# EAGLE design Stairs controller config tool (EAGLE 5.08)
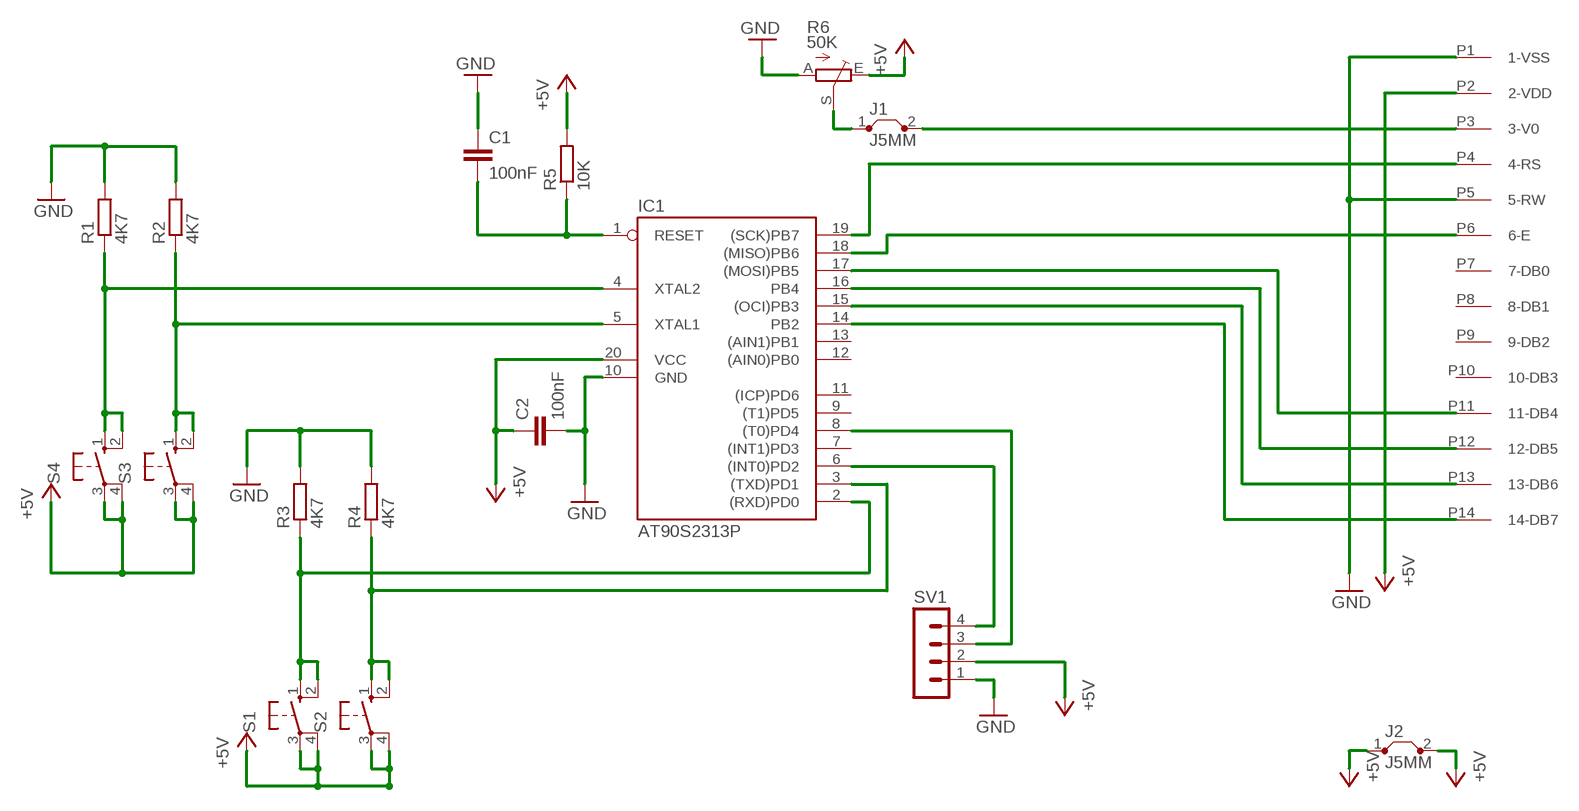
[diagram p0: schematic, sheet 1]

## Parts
C1  100nF  C-EU025-025X050  [C025-025X050]
C2  100nF  C-EU025-025X050  [C025-025X050]
IC1  AT90S2313P  [DIL20]
J1  J5MM  [05]
J2  J5MM  [05]
R1  4K7  R-EU_0207/12  [0207/12]
R2  4K7  R-EU_0207/12  [0207/12]
R3  4K7  R-EU_0207/12  [0207/12]
R4  4K7  R-EU_0207/12  [0207/12]
R5  10K  R-EU_0207/12  [0207/12]
R6  50K  TRIM_EU-B25P  [B25P]
S1  10-XX  [B3F-10XX]
S2  10-XX  [B3F-10XX]
S3  10-XX  [B3F-10XX]
S4  10-XX  [B3F-10XX]
SV1  MA04-1  [MA04-1]
U$1  16X2LCD  [NO_BACKLIGHT]

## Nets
+5V: C2.1 IC1.20(VCC) J2.1 J2.2 R5.2 R6.E S1.3(P) S1.4(P1) S2.3(P) S2.4(P1) S3.3(P) S3.4(P1) S4.3(P) S4.4(P1) SV1.2 U$1.P2(2-VDD)
GND: C1.1 C2.2 IC1.10(GND) R1.2 R2.2 R3.2 R4.2 R6.A SV1.1 U$1.P1(1-VSS) U$1.P5(5-RW)
N$1: IC1.19((SCK)PB7) U$1.P4(4-RS)
N$2: IC1.18((MISO)PB6) U$1.P6(6-E)
N$3: IC1.17((MOSI)PB5) U$1.P11(11-DB4)
N$4: IC1.16(PB4) U$1.P12(12-DB5)
N$5: IC1.15((OCI)PB3) U$1.P13(13-DB6)
N$6: IC1.14(PB2) U$1.P14(14-DB7)
N$7: IC1.4(XTAL2) R1.1 S4.1(S) S4.2(S1)
N$8: IC1.6((INT0)PD2) SV1.4
N$9: IC1.5(XTAL1) R2.1 S3.1(S) S3.2(S1)
N$10: IC1.8((T0)PD4) SV1.3
N$11: IC1.2((RXD)PD0) R3.1 S1.1(S) S1.2(S1)
N$12: IC1.3((TXD)PD1) R4.1 S2.1(S) S2.2(S1)
N$13: C1.2 IC1.1(RESET) R5.1
N$14: J1.1 R6.S
N$15: J1.2 U$1.P3(3-V0)
Unconnected: IC1.7((INT1)PD3) IC1.9((T1)PD5) IC1.11((ICP)PD6) IC1.12((AIN0)PB0) IC1.13((AIN1)PB1) U$1.P7(7-DB0) U$1.P8(8-DB1) U$1.P9(9-DB2) U$1.P10(10-DB3)

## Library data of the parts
C1 C2 = rcl:C-EU: CAPACITOR, European symbol
IC1 = atmel:AT90S2313: MICROCONTROLLER 2 Kbytes FLASH 128 bytes SRAM 128 bytes EEPROM UART
J1 J2 = jumper:J: Bridge
R1-R5 = rcl:R-EU_: RESISTOR, European symbol
R6 = pot:TRIM_EU-: POTENTIOMETER
S1-S4 = switch-omron:10-XX: OMRON SWITCH
SV1 = con-lstb:MA04-1: PIN HEADER
U$1 = lcd_nobacklight:16X2LCD: 16x2 LCD - no backlight

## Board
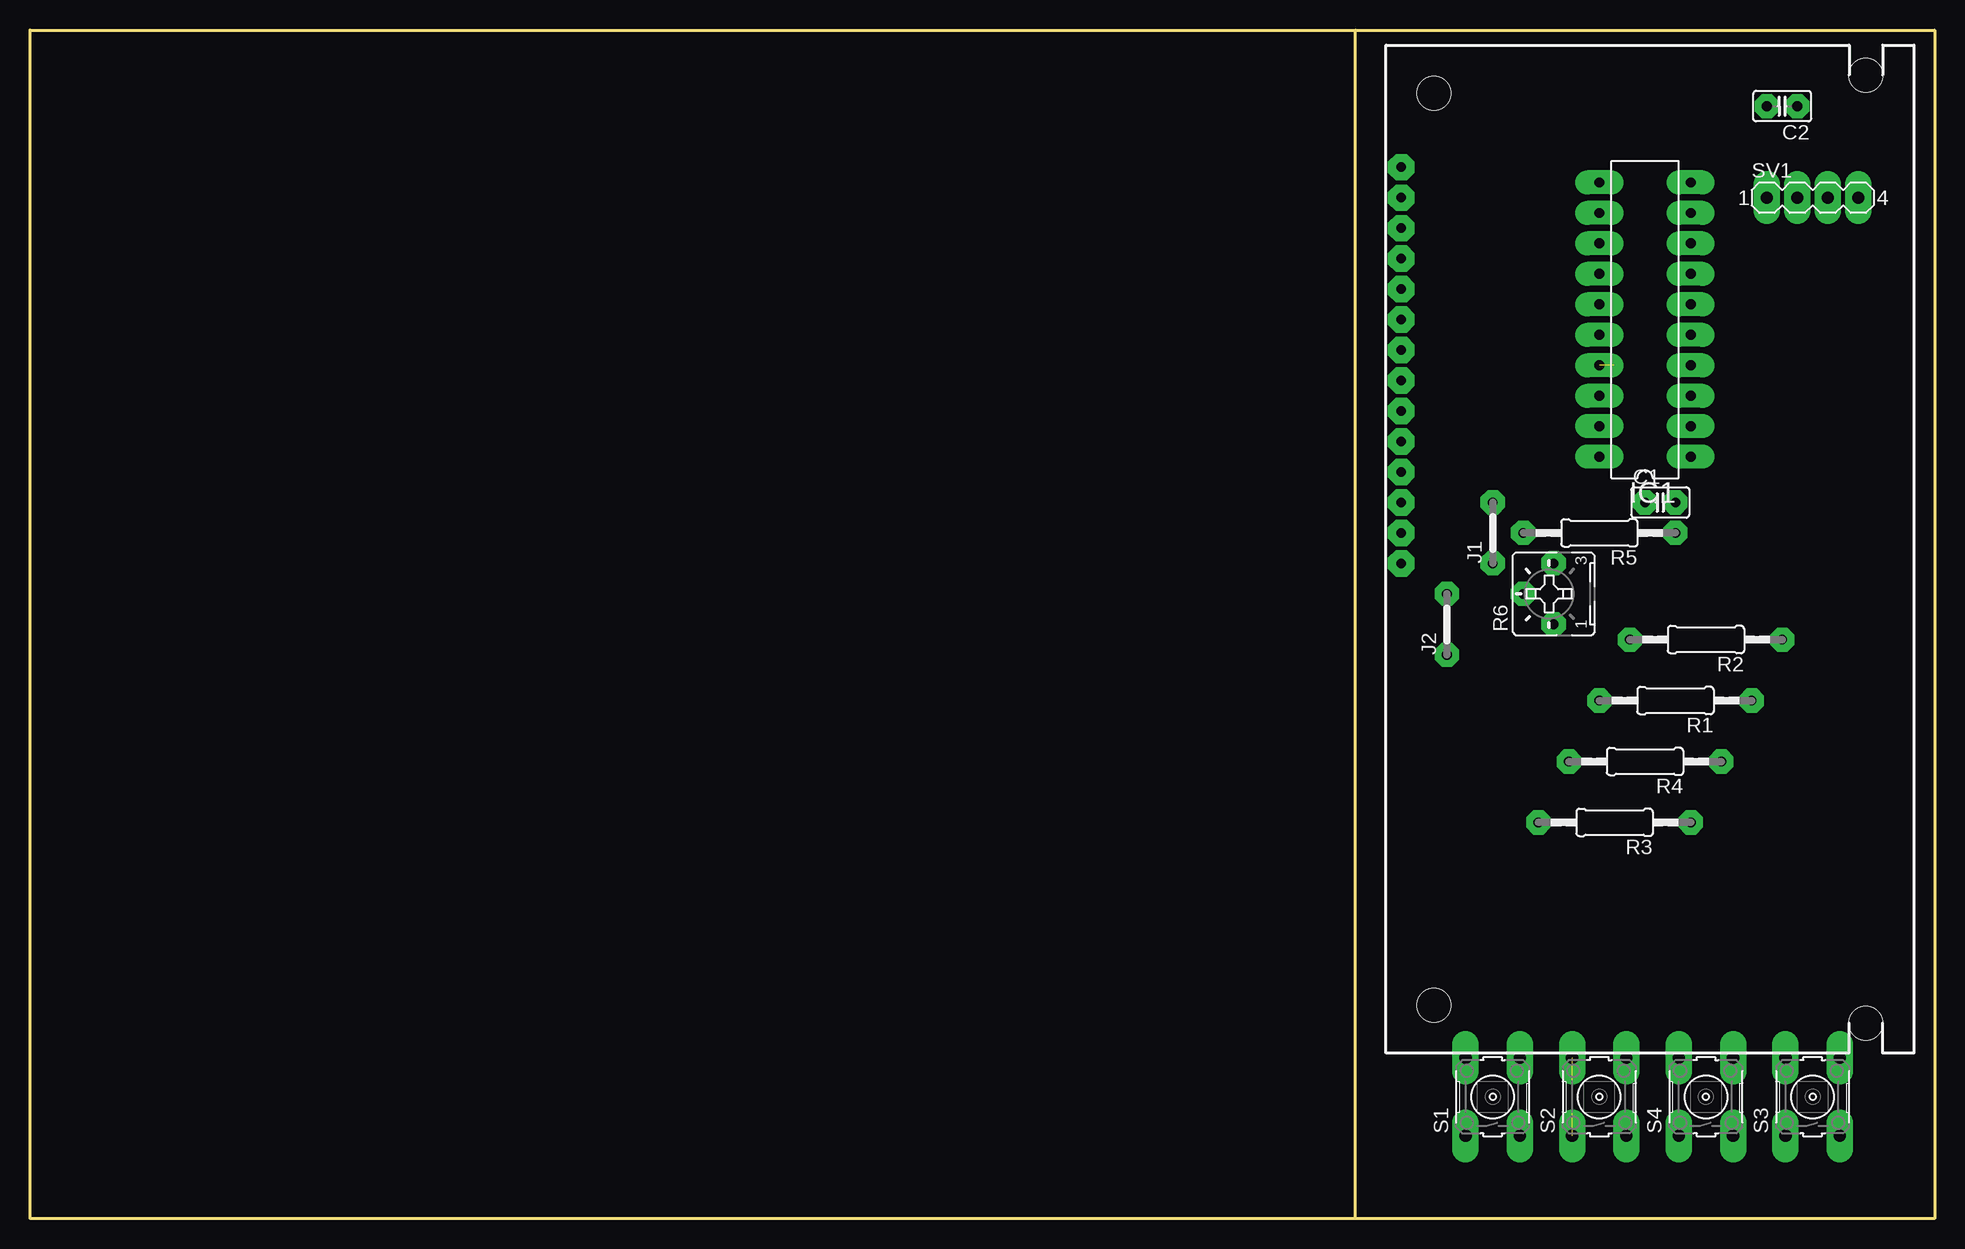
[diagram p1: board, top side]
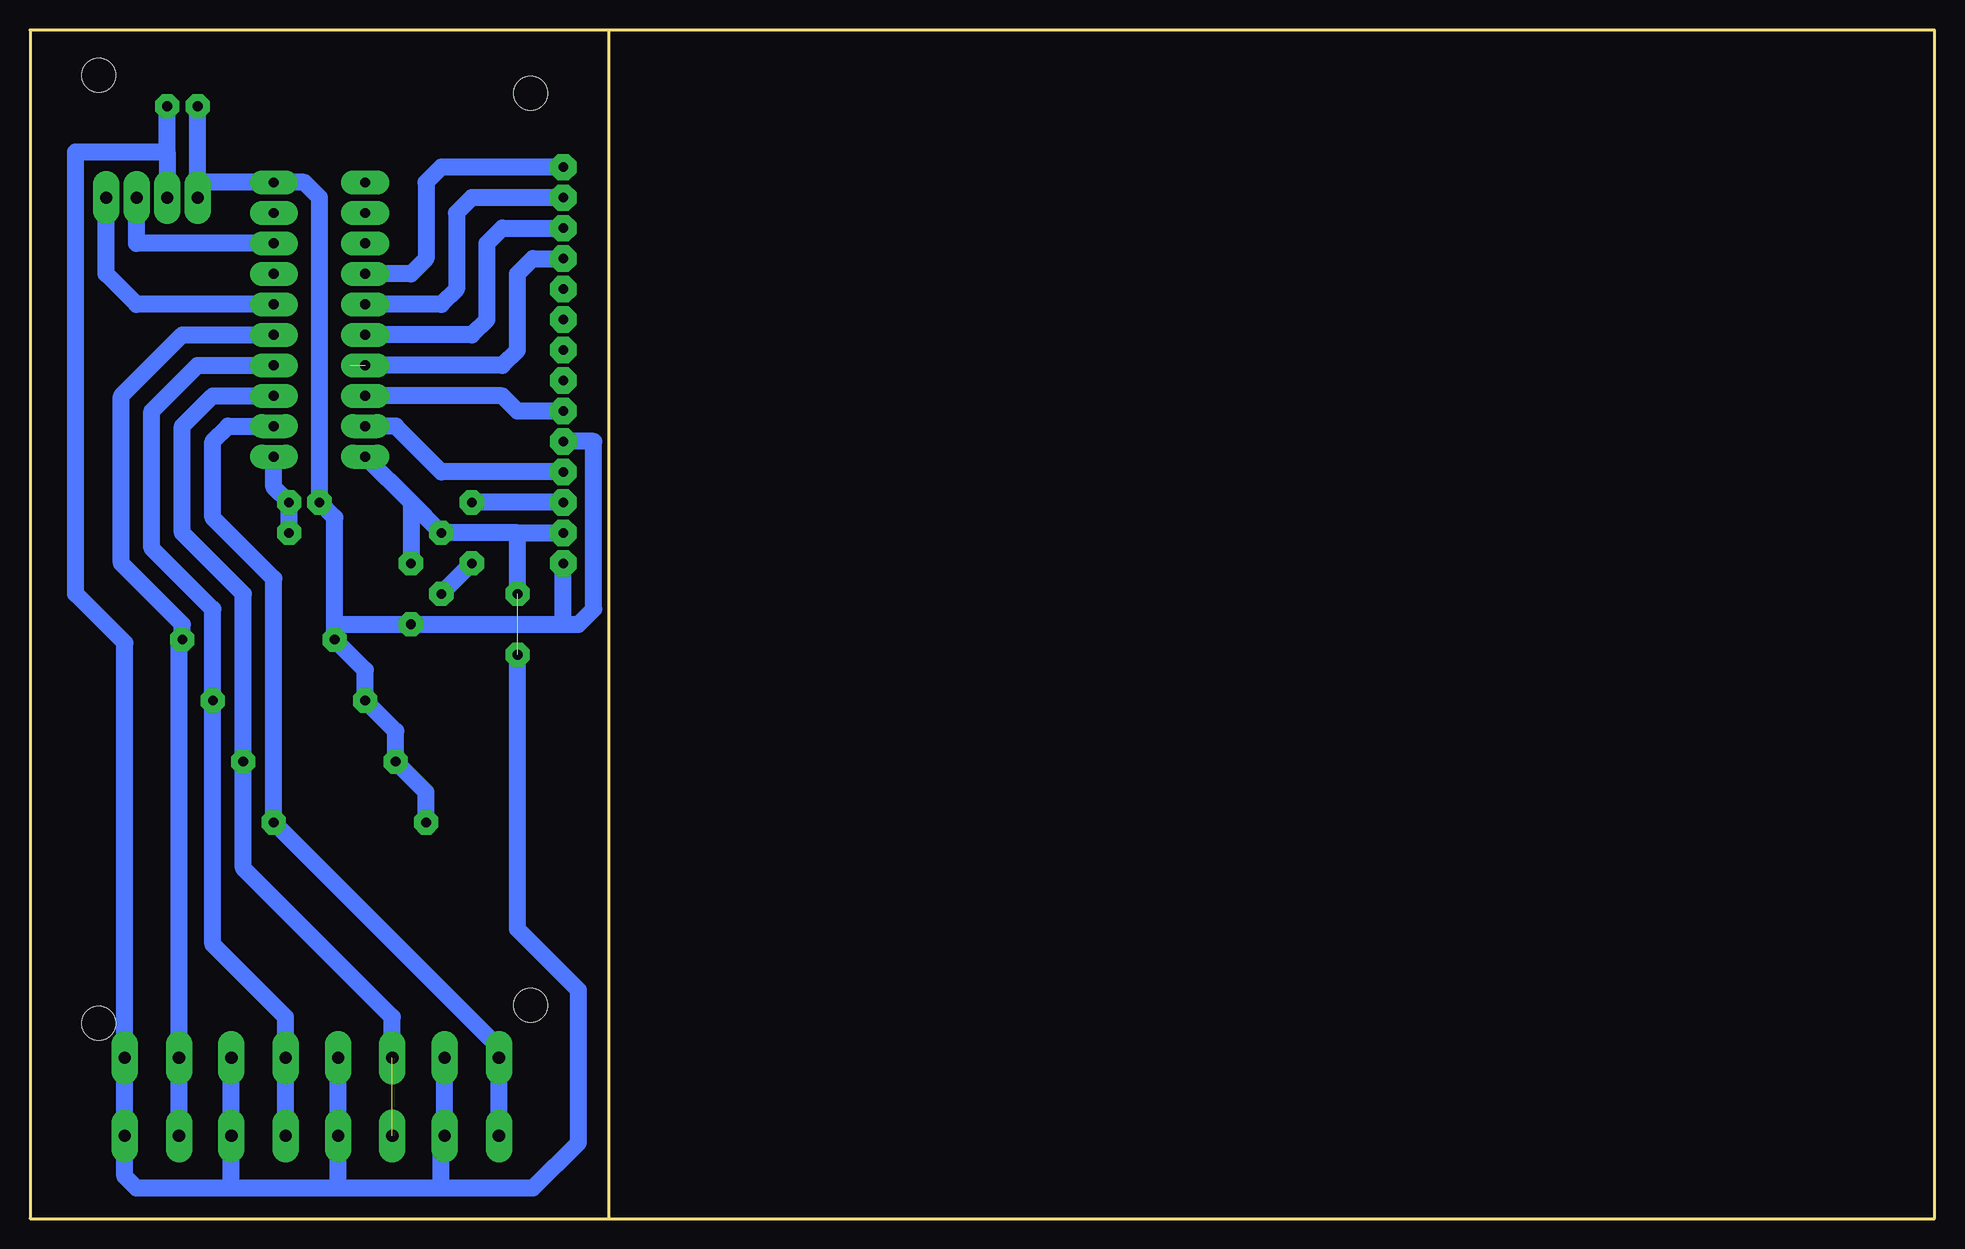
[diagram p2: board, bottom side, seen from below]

Size 158.75 x 99.06 mm. Coordinates in mm from the lower left corner, seen from the top.
Outline: 110.49,99.06 0,99.06 0,0 110.49,0
Outline: 110.49,99.06 158.75,99.06 158.75,0 110.49,0
Outline: 110.49,0 110.49,99.06
Copper layers (1*16): Top 1mm / dielectric 1.5mm / Bottom 1mm
Design rules "DRC settings middle": minimum track width 1.2mm, minimum drill 24mil, track to track 0.4mm, track to pad 0.4mm, pad to pad 0.4mm, via to via 0.4mm, smd to smd 8mil, copper to edge 0.5mm, drill to drill 0.5mm, minimum pad ring 0.6mm, minimum via ring 1mm, stop-mask expansion 4mil, vias tented up to drill 0mil, thermal gap 10mil

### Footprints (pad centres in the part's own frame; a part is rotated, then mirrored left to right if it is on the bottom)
C025-025X050 = drill 0.813 octagon: 1 -1.27,0; 2 1.27,0
DIL20 = drill 0.813 long: 1 -11.43,-3.81; 2 -8.89,-3.81; 3 -6.35,-3.81; 4 -3.81,-3.81; 5 -1.27,-3.81; 6 1.27,-3.81; 7 3.81,-3.81; 8 6.35,-3.81; 9 8.89,-3.81; 10 11.43,-3.81; 11 11.43,3.81; 12 8.89,3.81; 13 6.35,3.81; 14 3.81,3.81; 15 1.27,3.81; 16 -1.27,3.81; 17 -3.81,3.81; 18 -6.35,3.81; 19 -8.89,3.81; 20 -11.43,3.81
05 = drill 0.813 pad 1.6 octagon: 1 -2.54,0; 2 2.54,0
0207/12 = drill 0.813 octagon: 1 -6.35,0; 2 6.35,0
B25P = drill 0.813 octagon: A -2.54,0; E 2.54,0; S 0,2.54
B3F-10XX = drill 1.016 long: 1 -3.251,2.261; 2 3.251,2.261; 3 -3.251,-2.261; 4 3.251,-2.261
MA04-1 = drill 1.016 long: 1 -3.81,0; 2 -1.27,0; 3 1.27,0; 4 3.81,0
NO_BACKLIGHT = drill 0.8 pad 2.184 octagon: P1 43.18,1.27; P2 40.64,1.27; P3 38.1,1.27; P4 35.56,1.27; P5 33.02,1.27; P6 30.48,1.27; P7 27.94,1.27; P8 25.4,1.27; P9 22.86,1.27; P10 20.32,1.27; P11 17.78,1.27; P12 15.24,1.27; P13 12.7,1.27; P14 10.16,1.27 | hole 2.8: 4,4; 80,4; 2.5,40; 81.5,40

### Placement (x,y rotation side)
C1  135.89,59.69 0 top
C2  146.05,92.71 180 top
IC1  134.62,74.93 90 top
J1  121.92,57.15 90 top
J2  118.11,49.53 90 top
R1  137.16,43.18 180 top
R2  139.7,48.26 180 top
R3  132.08,33.02 180 top
R4  134.62,38.1 180 top
R5  130.81,57.15 180 top
R6  127,52.07 90 top
S1  121.92,10.16 90 top
S2  130.81,10.16 90 top
S3  148.59,10.16 90 top
S4  139.7,10.16 90 top
SV1  148.59,85.09 0 top
U$1  113.03,97.79 270 top

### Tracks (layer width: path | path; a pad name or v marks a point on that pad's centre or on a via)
+5V  (1 unrouted)
  Bottom 1.422: 147.32,88.9 SV1.2 | 147.32,88.9 154.94,88.9 154.94,52.07 150.85,47.98 S3.4 S3.3 150.85,3.53 149.86,2.54 142.24,2.54 | 133.35,2.54 142.24,2.54 | 133.35,2.54 133.07,2.82 S2.3 S2.4 | 142.24,2.54 141.96,2.82 S4.3 S4.4 | S1.4 S1.3 124.46,6.63 124.46,2.54 | 147.32,88.9 C2.1 | 127,59.69 R5.2 118.11,57.15 | 127,59.69 IC1.20 | 118.11,57.15 U$1.P2 | 127,59.69 R6.E | J2.1 118.11,24.13 113.03,19.05 113.03,6.35 116.84,2.54 124.46,2.54 | 124.46,2.54 133.35,2.54 | J2.2 118.11,57.15
GND
  Bottom 1.422: R3.2 125.73,35.56 R4.2 128.27,40.64 R1.2 130.81,45.72 R2.2 133.35,49.53 | 144.78,86.36 SV1.1 | 144.78,86.36 C2.2 | 144.78,86.36 IC1.10 135.89,86.36 134.62,85.09 C1.1 133.35,58.42 133.35,49.53 | 133.35,49.53 R6.A 114.3,49.53 | U$1.P5 111.76,64.77 111.76,50.8 113.03,49.53 114.3,49.53 | 114.3,49.53 U$1.P1
N$1
  Bottom 1.422: IC1.19 128.27,66.04 124.46,62.23 U$1.P4
N$2
  Bottom 1.422: IC1.18 119.38,68.58 118.11,67.31 U$1.P6
N$3  (1 unrouted)
  Bottom 1.422: U$1.P11 116.84,80.01 118.11,78.74 118.11,72.39 119.38,71.12 132.08,71.12
N$4
  Bottom 1.422: U$1.P12 119.38,82.55 120.65,81.28 120.65,74.93 121.92,73.66 IC1.16
N$5
  Bottom 1.422: U$1.P13 121.92,85.09 123.19,83.82 123.19,77.47 124.46,76.2 IC1.15
N$6
  Bottom 1.422: U$1.P14 124.46,87.63 125.73,86.36 125.73,80.01 127,78.74 IC1.14
N$7
  Bottom 1.422: S4.1 S4.2 137.44,16.79 143.51,22.86 R1.1 143.51,50.8 148.59,55.88 148.59,67.31 144.78,71.12 IC1.4
N$8
  Bottom 1.422: IC1.6 149.86,76.2 152.4,78.74 SV1.4
N$9
  Bottom 1.422: S3.1 S3.2 146.33,47.98 R2.1 146.05,49.53 151.13,54.61 151.13,68.58 146.05,73.66 IC1.5
N$10
  Bottom 1.422: IC1.8 149.86,81.28 SV1.3
N$11
  Bottom 1.422: S1.1 S1.2 119.66,14.25 R3.1 138.43,53.34 143.51,58.42 143.51,64.77 142.24,66.04 IC1.2
N$12  (1 unrouted)
  Bottom 1.422: S2.2 128.55,16.79 140.97,29.21 R4.1 140.97,52.07 146.05,57.15 146.05,66.04 143.51,68.58 IC1.3
N$13
  Bottom 1.422: IC1.1 138.43,60.96 C1.2 R5.1
N$14
  Bottom 1.422: J1.1 R6.S
N$15
  Bottom 1.422: U$1.P3 J1.2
